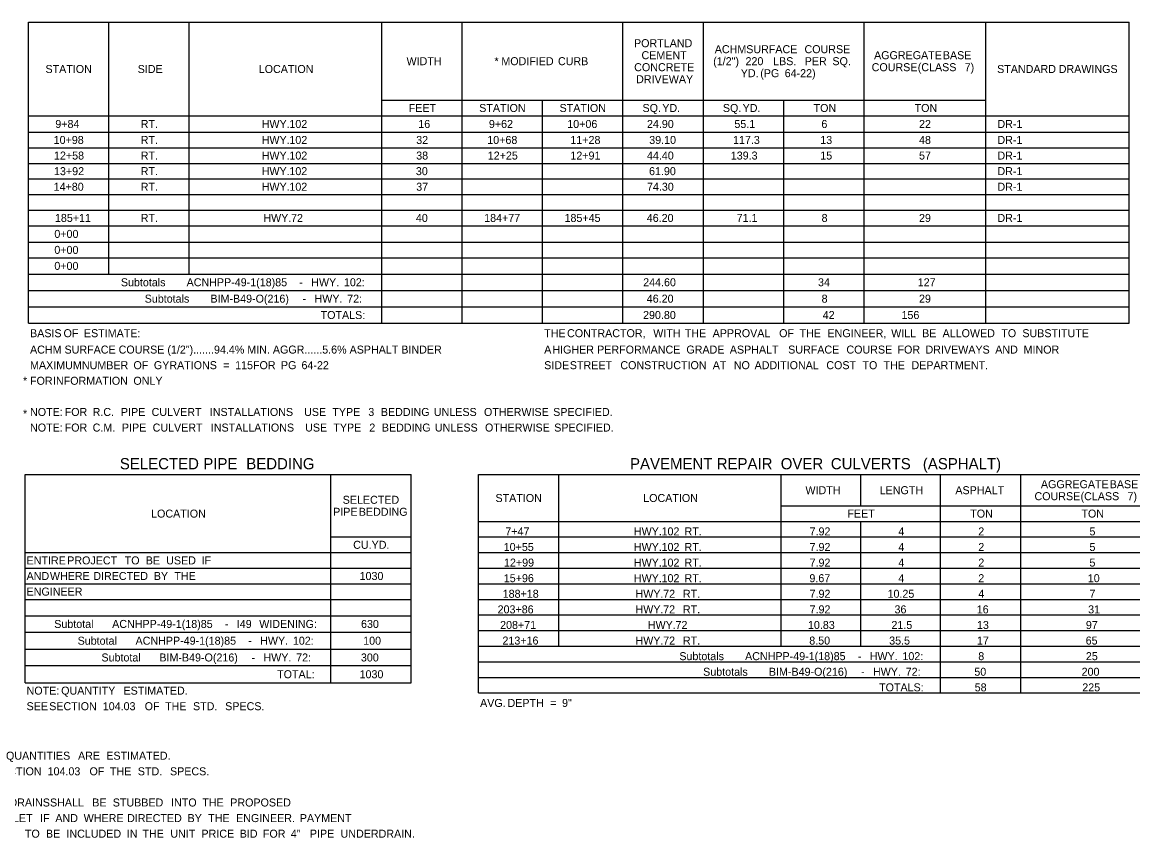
# Model space of a CAD drawing. Extents: x 1226561 to 1228164, y 151309 to 152305.
# Drawn here: x 1226933 to 1227627, y 151326 to 151836 of the extents above; entities that cross this region are included whole.
import ezdxf

# ---------------------------------------------------------------- set-up
doc = ezdxf.new("R2010")
doc.units = 0
doc.layers.add('R_Dimension', color=7, linetype='Continuous')

msp = doc.modelspace()

# ---------------------------------------------------------------- linework, layer by layer
at = {"layer": 'R_Dimension'}
for p, q in [((1226937.37, 151835.6), (1227625.23, 151835.6)), ((1226937.37, 151647.43), (1226937.37, 151835.6)), ((1226987.58, 151678.14), (1226987.58, 151835.6)), ((1227037.79, 151678.14), (1227037.79, 151835.6)), ((1227158.21, 151647.43), (1227158.21, 151835.6)), ((1227208.42, 151647.43), (1227208.42, 151835.6)), ((1227308.84, 151647.43), (1227308.84, 151835.6)), ((1227359.06, 151647.43), (1227359.06, 151835.6)), ((1227459.48, 151647.43), (1227459.48, 151835.6)), ((1227535.53, 151647.43), (1227535.53, 151835.6)), ((1227625.23, 151647.43), (1227625.23, 151835.6)), ((1227158.21, 151786.85), (1227535.53, 151786.85)), ((1227258.63, 151647.43), (1227258.63, 151786.85)), ((1227409.27, 151647.43), (1227409.27, 151786.85)), ((1226937.37, 151777.1), (1227625.23, 151777.1)), ((1227535.53, 151777.1), (1227625.23, 151777.1)), ((1226937.37, 151766.86), (1227625.23, 151766.86)), ((1226937.37, 151757.11), (1227625.23, 151757.11)), ((1226937.37, 151747.36), (1227625.23, 151747.36)), ((1226937.37, 151737.61), (1227625.23, 151737.61)), ((1226937.37, 151727.86), (1227625.23, 151727.86)), ((1226937.37, 151718.11), (1227625.23, 151718.11)), ((1226937.37, 151708.36), (1227625.23, 151708.36)), ((1226937.37, 151698.13), (1227625.23, 151698.13)), ((1226937.37, 151688.38), (1227625.23, 151688.38)), ((1226937.37, 151678.14), (1227625.23, 151678.14)), ((1226937.37, 151678.14), (1227625.23, 151678.14)), ((1226937.37, 151667.9), (1227625.23, 151667.9)), ((1226937.37, 151657.66), (1227625.23, 151657.66)), ((1226937.37, 151647.43), (1227625.23, 151647.43)), ((1226935.2, 151552.78), (1227176.51, 151552.78)), ((1226935.2, 151422.62), (1226935.2, 151552.78)), ((1227126.3, 151422.62), (1227126.3, 151552.78)), ((1227176.51, 151422.62), (1227176.51, 151552.78)), ((1227218.58, 151552.78), (1227646.11, 151552.78)), ((1227218.58, 151416.28), (1227218.58, 151552.78)), ((1227268.79, 151445.53), (1227268.79, 151552.78)), ((1227407.73, 151445.53), (1227407.73, 151552.78)), ((1227457.45, 151533.28), (1227457.45, 151552.78)), ((1227507.18, 151416.28), (1227507.18, 151552.78)), ((1227557.39, 151416.28), (1227557.39, 151552.78)), ((1227407.73, 151533.28), (1227646.11, 151533.28)), ((1227218.58, 151523.53), (1227646.11, 151523.53)), ((1227457.45, 151445.53), (1227457.45, 151523.53)), ((1227126.3, 151513.78), (1227176.51, 151513.78)), ((1227218.58, 151513.78), (1227646.11, 151513.78)), ((1226935.2, 151504.03), (1227176.51, 151504.03)), ((1227218.58, 151504.03), (1227646.11, 151504.03)), ((1226935.2, 151494.28), (1227176.51, 151494.28)), ((1227218.58, 151494.28), (1227646.11, 151494.28)), ((1226935.2, 151484.53), (1227176.51, 151484.53)), ((1227218.58, 151484.53), (1227646.11, 151484.53)), ((1226935.2, 151474.78), (1227176.51, 151474.78)), ((1227218.58, 151474.78), (1227646.11, 151474.78)), ((1226935.2, 151464.54), (1227176.51, 151464.54)), ((1227218.58, 151465.03), (1227646.11, 151465.03)), ((1226935.2, 151454.3), (1227176.51, 151454.3)), ((1227218.58, 151455.28), (1227646.11, 151455.28)), ((1227218.58, 151445.53), (1227646.11, 151445.53)), ((1226935.2, 151443.58), (1227176.51, 151443.58)), ((1226935.2, 151433.34), (1227176.51, 151433.34)), ((1227218.58, 151435.78), (1227646.11, 151435.78)), ((1227218.58, 151426.03), (1227646.11, 151426.03)), ((1226935.2, 151422.62), (1227176.51, 151422.62)), ((1227218.58, 151416.28), (1227646.11, 151416.28))]:
    msp.add_line(p, q, dxfattribs=at)

# ---------------------------------------------------------------- texts
for s, height, p in [('PORTLAND', 5, (1227315.74, 151819.98)), ('ACHM', 5, (1227366.2, 151816.23)), (' SURFACE', 5, (1227383.99, 151816.23)), (' COURSE', 5, (1227420.41, 151816.23)), ('WIDTH', 5, (1227173.59, 151808.73)), ('*', 5, (1227228.55, 151808.73)), (' MODIFIED', 5, (1227230.99, 151808.73)), (' CURB', 5, (1227266.35, 151808.73)), ('CEMENT', 5, (1227320.43, 151812.48)), ('(1/2")', 5, (1227365.21, 151808.73)), (' 220', 5, (1227383.56, 151808.73)), (' LBS.', 5, (1227400.8, 151808.73)), (' PER', 5, (1227420.53, 151808.73)), (' SQ.', 5, (1227437.85, 151808.73)), ('AGGREGATE', 5, (1227465.75, 151812.48)), (' BASE', 5, (1227506.86, 151812.48)), ('STATION', 5, (1226947.97, 151803.85)), ('SIDE', 5, (1227005.6, 151803.85)), ('LOCATION', 5, (1227081.25, 151803.85)), ('CONCRETE', 5, (1227315.84, 151804.98)), ('YD.', 5, (1227382.44, 151801.23)), (' (PG', 5, (1227392.75, 151801.23)), (' 64-22)', 5, (1227408.03, 151801.23)), ('COURSE', 5, (1227464.24, 151804.98)), (' (CLASS', 5, (1227491.17, 151804.98)), (' 7)', 5, (1227520.5, 151804.98)), ('STANDARD', 5, (1227542.63, 151803.85)), (' DRAWINGS', 5, (1227579.28, 151803.85)), ('DRIVEWAY', 5, (1227317.02, 151797.48)), ('FEET', 5, (1227174.95, 151779.48)), ('STATION', 5, (1227219.02, 151779.48)), ('STATION', 5, (1227269.23, 151779.48)), ('SQ.', 5, (1227321.06, 151779.48)), (' YD.', 5, (1227331.53, 151779.48)), ('SQ.', 5, (1227371.27, 151779.48)), (' YD.', 5, (1227381.74, 151779.48)), ('TON', 5, (1227427.94, 151779.48)), ('TON', 5, (1227491.07, 151779.48)), ('9+84', 5, (1226954.13, 151769.48)), ('RT.', 5, (1227007.49, 151769.48)), ('HWY.', 5, (1227083.1, 151769.48)), (' 102', 5, (1227098.53, 151769.48)), ('16', 5, (1227180.93, 151769.48)), ('9+62', 5, (1227225.06, 151769.48)), ('10+06', 5, (1227274.03, 151769.48)), ('24.90', 5, (1227323.83, 151769.48)), ('55.1', 5, (1227378.45, 151769.48)), ('6', 5, (1227432.82, 151769.48)), ('22', 5, (1227493.84, 151769.48)), ('DR-1', 5, (1227542.82, 151769.48)), ('10+98', 5, (1226953.1, 151759.49)), ('RT.', 5, (1227007.49, 151759.49)), ('HWY.', 5, (1227083.1, 151759.49)), (' 102', 5, (1227098.53, 151759.49)), ('32', 5, (1227179.65, 151759.49)), ('10+68', 5, (1227224.04, 151759.49)), ('11+28', 5, (1227275.98, 151759.49)), ('39.10', 5, (1227325.25, 151759.49)), ('117.3', 5, (1227377.63, 151759.49)), ('13', 5, (1227432.13, 151759.49)), ('48', 5, (1227493.84, 151759.49)), ('DR-1', 5, (1227542.82, 151759.49)), ('12+58', 5, (1226953.3, 151749.74)), ('RT.', 5, (1227007.49, 151749.74)), ('HWY.', 5, (1227083.1, 151749.74)), (' 102', 5, (1227098.53, 151749.74)), ('38', 5, (1227179.65, 151749.74)), ('12+25', 5, (1227224.35, 151749.74)), ('12+91', 5, (1227275.98, 151749.74)), ('44.40', 5, (1227323.83, 151749.74)), ('139.3', 5, (1227376.21, 151749.74)), ('15', 5, (1227432.13, 151749.74)), ('57', 5, (1227493.84, 151749.74)), ('DR-1', 5, (1227542.82, 151749.74)), ('13+92', 5, (1226953.3, 151739.99)), ('RT.', 5, (1227007.49, 151739.99)), ('HWY.', 5, (1227083.1, 151739.99)), (' 102', 5, (1227098.53, 151739.99)), ('30', 5, (1227179.43, 151739.99)), ('61.90', 5, (1227325.13, 151739.99)), ('DR-1', 5, (1227542.82, 151739.99)), ('14+80', 5, (1226953.08, 151730.24)), ('RT.', 5, (1227007.49, 151730.24)), ('HWY.', 5, (1227083.1, 151730.24)), (' 102', 5, (1227098.53, 151730.24)), ('37', 5, (1227179.65, 151730.24)), ('74.30', 5, (1227323.83, 151730.24)), ('DR-1', 5, (1227542.82, 151730.24)), ('185+11', 5, (1226953.89, 151710.74)), ('RT.', 5, (1227007.49, 151710.74)), ('HWY.', 5, (1227084.12, 151710.74)), (' 72', 5, (1227099.55, 151710.74)), ('40', 5, (1227179.43, 151710.74)), ('184+77', 5, (1227222.11, 151710.74)), ('185+45', 5, (1227272.32, 151710.74)), ('46.20', 5, (1227323.71, 151710.74)), ('71.1', 5, (1227379.87, 151710.74)), ('8', 5, (1227432.96, 151710.74)), ('29', 5, (1227493.82, 151710.74)), ('DR-1', 5, (1227542.82, 151710.74)), ('0+00', 5, (1226953.52, 151700.75)), ('0+00', 5, (1226953.52, 151690.75)), ('0+00', 5, (1226953.52, 151680.76)), ('Subtotals', 5, (1226995.1, 151670.52)), (' ACNHPP-49-1(18)85', 5, (1227034.31, 151670.52)), (' HWY.', 5, (1227112.19, 151670.52)), (' 102:', 5, (1227132.62, 151670.52)), ('244.60', 5, (1227321.47, 151670.52)), ('34', 5, (1227430.71, 151670.52)), ('127', 5, (1227493.02, 151670.52)), (' -', 5, (1227104.75, 151670.52)), ('Subtotals', 5, (1227009.98, 151660.28)), (' BIM-B49-O(216)', 5, (1227049.19, 151660.28)), (' -', 5, (1227106.79, 151660.28)), (' HWY.', 5, (1227114.23, 151660.28)), (' 72:', 5, (1227134.67, 151660.28)), ('46.20', 5, (1227323.71, 151660.28)), ('8', 5, (1227432.96, 151660.28)), ('29', 5, (1227493.82, 151660.28)), ('TOTALS:', 5, (1227119.9, 151650.05)), ('290.80', 5, (1227321.39, 151650.05)), ('42', 5, (1227433.64, 151650.05)), ('156', 5, (1227482.88, 151650.05)), ('BASIS', 5, (1226938.34, 151638.68)), (' OF', 5, (1226957.4, 151638.68)), (' ESTIMATE:', 5, (1226970.15, 151638.68)), ('THE', 5, (1227259.61, 151638.68)), (' CONTRACTOR,', 5, (1227272.05, 151638.68)), (' WITH', 5, (1227325.87, 151638.68)), (' THE', 5, (1227345.59, 151638.68)), (' APPROVAL', 5, (1227363.03, 151638.68)), (' OF', 5, (1227404.57, 151638.68)), (' THE', 5, (1227417.32, 151638.68)), (' ENGINEER,', 5, (1227434.76, 151638.68)), (' WILL', 5, (1227474.57, 151638.68)), (' BE', 5, (1227493.9, 151638.68)), (' ALLOWED', 5, (1227506.69, 151638.68)), (' TO', 5, (1227543.39, 151638.68)), (' SUBSTITUTE', 5, (1227556.54, 151638.68)), ('ACHM SURFACE COURSE (1/2").......94.4% MIN. AGGR......5.6% ASPHALT BINDER', 5, (1226938.34, 151628.44)), ('A', 5, (1227259.61, 151628.44)), (' HIGHER', 5, (1227262.87, 151628.44)), (' PERFORMANCE', 5, (1227290.83, 151628.44)), (' GRADE', 5, (1227346.61, 151628.44)), (' ASPHALT', 5, (1227373.74, 151628.44)), (' SURFACE', 5, (1227410.2, 151628.44)), (' COURSE', 5, (1227446.61, 151628.44)), (' FOR', 5, (1227478.54, 151628.44)), (' DRIVEWAYS', 5, (1227496.02, 151628.44)), (' AND', 5, (1227539.61, 151628.44)), (' MINOR', 5, (1227557.32, 151628.44)), ('MAXIMUM', 5, (1226938.34, 151618.69)), (' NUMBER', 5, (1226968.89, 151618.69)), (' OF', 5, (1227001.1, 151618.69)), (' GYRATIONS', 5, (1227013.86, 151618.69)), (' =', 5, (1227057.2, 151618.69)), (' 115', 5, (1227064.64, 151618.69)), (' FOR', 5, (1227075.78, 151618.69)), (' PG', 5, (1227093.26, 151618.69)), (' 64-22', 5, (1227106.1, 151618.69)), ('SIDE', 5, (1227259.61, 151618.69)), (' STREET', 5, (1227273.78, 151618.69)), (' CONSTRUCTION', 5, (1227305.35, 151618.69)), (' AT', 5, (1227363.07, 151618.69)), (' NO', 5, (1227376.22, 151618.69)), (' ADDITIONAL', 5, (1227389.21, 151618.69)), (' COST', 5, (1227434.05, 151618.69)), (' TO', 5, (1227456.65, 151618.69)), (' THE', 5, (1227469.8, 151618.69)), (' DEPARTMENT.', 5, (1227487.24, 151618.69)), ('*', 5, (1226933.95, 151608.94)), ('FOR', 5, (1226938.34, 151608.94)), (' INFORMATION', 5, (1226950.82, 151608.94)), (' ONLY', 5, (1227001.06, 151608.94)), ('*', 5, (1226933.95, 151588.44)), ('NOTE:', 5, (1226938.34, 151589.44)), (' FOR', 5, (1226958.11, 151589.44)), (' R.C.', 5, (1226975.59, 151589.44)), (' PIPE', 5, (1226993.26, 151589.44)), (' CULVERT', 5, (1227012.44, 151589.44)), (' INSTALLATIONS', 5, (1227048.82, 151589.44)), (' USE', 5, (1227107.75, 151589.44)), (' TYPE', 5, (1227125.35, 151589.44)), (' 3', 5, (1227147.83, 151589.44)), (' BEDDING', 5, (1227155.67, 151589.44)), (' UNLESS', 5, (1227188.82, 151589.44)), (' OTHERWISE', 5, (1227220.12, 151589.44)), (' SPECIFIED.', 5, (1227263.38, 151589.44)), ('NOTE:', 5, (1226938.34, 151579.69)), (' FOR', 5, (1226958.11, 151579.69)), (' C.M.', 5, (1226975.59, 151579.69)), (' PIPE', 5, (1226993.89, 151579.69)), (' CULVERT', 5, (1227013.07, 151579.69)), (' INSTALLATIONS', 5, (1227049.45, 151579.69)), (' USE', 5, (1227108.38, 151579.69)), (' TYPE', 5, (1227125.98, 151579.69)), (' 2', 5, (1227148.46, 151579.69)), (' BEDDING', 5, (1227156.3, 151579.69)), (' UNLESS', 5, (1227189.45, 151579.69)), (' OTHERWISE', 5, (1227220.75, 151579.69)), (' SPECIFIED.', 5, (1227264.01, 151579.69)), ('SELECTED', 7, (1226994.45, 151556.1)), (' PIPE', 7, (1227044, 151556.1)), (' BEDDING', 7, (1227070.84, 151556.1)), ('PAVEMENT', 7, (1227313.26, 151556.1)), (' REPAIR', 7, (1227364.8, 151556.1)), (' OVER', 7, (1227404.81, 151556.1)), (' CULVERTS', 7, (1227436.12, 151556.1)), (' (ASPHALT)', 7, (1227493.61, 151556.1)), ('AGGREGATE', 5, (1227570, 151544.28)), (' BASE', 5, (1227611.1, 151544.28)), ('WIDTH', 5, (1227422.86, 151540.53)), ('LENGTH', 5, (1227469.24, 151540.53)), ('ASPHALT', 5, (1227516.55, 151540.53)), ('COURSE', 5, (1227565.98, 151536.78)), (' (CLASS', 5, (1227592.91, 151536.78)), (' 7)', 5, (1227622.24, 151536.78)), ('SELECTED', 5, (1227133.7, 151534.53)), ('STATION', 5, (1227229.17, 151535.65)), ('LOCATION', 5, (1227321.5, 151535.65)), ('LOCATION', 5, (1227013.99, 151525.9)), ('PIPE', 5, (1227127.74, 151527.03)), (' BEDDING', 5, (1227141.91, 151527.03)), ('FEET', 5, (1227449.08, 151525.9)), ('TON', 5, (1227525.84, 151525.9)), ('TON', 5, (1227595.31, 151525.9)), ('7+47', 5, (1227235.34, 151514.78)), ('HWY.', 5, (1227315.66, 151514.78)), (' 102', 5, (1227331.09, 151514.78)), (' RT.', 5, (1227345.46, 151514.78)), ('7.92', 5, (1227425.46, 151514.78)), ('4', 5, (1227480.9, 151514.78)), ('2', 5, (1227530.86, 151514.78)), ('5', 5, (1227600.33, 151514.78)), ('CU.YD.', 5, (1227140.26, 151506.4)), ('10+55', 5, (1227234.31, 151505.03)), ('HWY.', 5, (1227315.66, 151505.03)), (' 102', 5, (1227331.09, 151505.03)), (' RT.', 5, (1227345.46, 151505.03)), ('7.92', 5, (1227425.46, 151505.03)), ('4', 5, (1227480.9, 151505.03)), ('2', 5, (1227530.86, 151505.03)), ('5', 5, (1227600.33, 151505.03)), ('ENTIRE', 5, (1226936.17, 151496.65)), (' PROJECT', 5, (1226959.71, 151496.65)), (' TO', 5, (1226995.62, 151496.65)), (' BE', 5, (1227008.77, 151496.65)), (' USED', 5, (1227021.56, 151496.65)), (' IF', 5, (1227043.69, 151496.65)), ('12+99', 5, (1227234.49, 151495.28)), ('HWY.', 5, (1227315.66, 151495.28)), (' 102', 5, (1227331.09, 151495.28)), (' RT.', 5, (1227345.46, 151495.28)), ('7.92', 5, (1227425.46, 151495.28)), ('4', 5, (1227480.9, 151495.28)), ('2', 5, (1227530.86, 151495.28)), ('5', 5, (1227600.33, 151495.28)), ('AND', 5, (1226936.17, 151486.9)), (' WHERE', 5, (1226948.89, 151486.9)), (' DIRECTED', 5, (1226976.01, 151486.9)), (' BY', 5, (1227013.81, 151486.9)), (' THE', 5, (1227026.68, 151486.9)), ('1030', 5, (1227144.26, 151486.9)), ('15+96', 5, (1227234.37, 151485.53)), ('HWY.', 5, (1227315.66, 151485.53)), (' 102', 5, (1227331.09, 151485.53)), (' RT.', 5, (1227345.46, 151485.53)), ('9.67', 5, (1227425.34, 151485.53)), ('4', 5, (1227480.9, 151485.53)), ('2', 5, (1227530.86, 151485.53)), ('10', 5, (1227599.29, 151485.53)), ('ENGINEER', 5, (1226936.17, 151477.15)), ('188+18', 5, (1227233.68, 151475.78)), ('HWY.', 5, (1227316.68, 151475.78)), (' 72', 5, (1227332.11, 151475.78)), (' RT.', 5, (1227344.44, 151475.78)), ('7.92', 5, (1227425.46, 151475.78)), ('10.25', 5, (1227474.16, 151475.78)), ('4', 5, (1227530.86, 151475.78)), ('7', 5, (1227600.33, 151475.78)), ('203+86', 5, (1227230.51, 151466.03)), ('HWY.', 5, (1227316.68, 151466.03)), (' 72', 5, (1227332.11, 151466.03)), (' RT.', 5, (1227344.44, 151466.03)), ('7.92', 5, (1227425.46, 151466.03)), ('36', 5, (1227478.51, 151466.03)), ('16', 5, (1227529.9, 151466.03)), ('31', 5, (1227599.51, 151466.03)), ('Subtotal', 5, (1226953.47, 151456.92)), (' ACNHPP-49-1(18)85', 5, (1226987.8, 151456.92)), (' -', 5, (1227058.23, 151456.92)), (' I49', 5, (1227065.67, 151456.92)), (' WIDENING:', 5, (1227079.69, 151456.92)), ('630', 5, (1227145.16, 151456.92)), ('208+71', 5, (1227232.07, 151456.28)), ('HWY.', 5, (1227324.38, 151456.28)), (' 72', 5, (1227339.81, 151456.28)), ('10.83', 5, (1227424.44, 151456.28)), ('21.5', 5, (1227476.6, 151456.28)), ('13', 5, (1227530.04, 151456.28)), ('97', 5, (1227598.09, 151456.28)), ('Subtotal', 5, (1226968.07, 151446.44)), (' ACNHPP-49-1(18)85', 5, (1227002.4, 151446.44)), (' HWY.', 5, (1227080.28, 151446.44)), (' 102:', 5, (1227100.71, 151446.44)), ('100', 5, (1227146.5, 151446.44)), ('213+16', 5, (1227233.54, 151446.53)), ('HWY.', 5, (1227316.68, 151446.53)), (' 72', 5, (1227332.11, 151446.53)), (' RT.', 5, (1227344.44, 151446.53)), ('8.50', 5, (1227425.25, 151446.53)), ('35.5', 5, (1227475.19, 151446.53)), ('17', 5, (1227530.04, 151446.53)), ('65', 5, (1227597.97, 151446.53)), (' -', 5, (1227072.84, 151446.44)), ('Subtotal', 5, (1226982.95, 151435.96)), (' BIM-B49-O(216)', 5, (1227017.28, 151435.96)), (' -', 5, (1227074.88, 151435.96)), (' HWY.', 5, (1227082.32, 151435.96)), (' 72:', 5, (1227102.76, 151435.96)), ('300', 5, (1227145.08, 151435.96)), ('Subtotals', 5, (1227344.07, 151436.78)), (' ACNHPP-49-1(18)85', 5, (1227383.28, 151436.78)), (' -', 5, (1227453.72, 151436.78)), (' HWY.', 5, (1227461.16, 151436.78)), (' 102:', 5, (1227481.59, 151436.78)), ('8', 5, (1227530.86, 151436.78)), ('25', 5, (1227598.09, 151436.78)), ('TOTAL:', 5, (1227092.72, 151425.48)), ('1030', 5, (1227144.26, 151425.48)), ('Subtotals', 5, (1227358.95, 151427.03)), (' BIM-B49-O(216)', 5, (1227398.16, 151427.03)), (' HWY.', 5, (1227463.2, 151427.03)), (' 72:', 5, (1227483.64, 151427.03)), ('50', 5, (1227528.4, 151427.03)), ('200', 5, (1227595.43, 151427.03)), (' -', 5, (1227455.76, 151427.03)), ('NOTE:', 5, (1226936.17, 151415.24)), (' QUANTITY', 5, (1226955.93, 151415.24)), (' ESTIMATED.', 5, (1226994.87, 151415.24)), ('TOTALS:', 5, (1227468.87, 151417.28)), ('58', 5, (1227528.62, 151417.28)), ('225', 5, (1227595.84, 151417.28)), ('SEE', 5, (1226936.17, 151405.49)), (' SECTION', 5, (1226948.45, 151405.49)), (' 104.03', 5, (1226981.92, 151405.49)), (' OF', 5, (1227008.1, 151405.49)), (' THE', 5, (1227020.86, 151405.49)), (' STD.', 5, (1227038.3, 151405.49)), (' SPECS.', 5, (1227058.41, 151405.49)), ('AVG.', 5, (1227219.55, 151407.53)), (' DEPTH', 5, (1227234.83, 151407.53)), (' =', 5, (1227261.48, 151407.53)), (' 9"', 5, (1227268.92, 151407.53)), (' QUANTITIES', 5, (1226921.46, 151374.55)), (' ARE', 5, (1226966.46, 151374.55)), (' ESTIMATED.', 5, (1226984.14, 151374.55)), (' SECTION', 5, (1226913.98, 151364.8)), (' 104.03', 5, (1226947.44, 151364.8)), (' OF', 5, (1226973.62, 151364.8)), (' THE', 5, (1226986.38, 151364.8)), (' STD.', 5, (1227003.82, 151364.8)), (' SPECS.', 5, (1227023.94, 151364.8)), ('UNDERDRAINS', 5, (1226901.7, 151345.3)), (' SHALL', 5, (1226948.94, 151345.3)), (' BE', 5, (1226975.36, 151345.3)), (' STUBBED', 5, (1226988.15, 151345.3)), (' INTO', 5, (1227024.61, 151345.3)), (' THE', 5, (1227044.14, 151345.3)), (' PROPOSED', 5, (1227061.58, 151345.3)), (' INLET', 5, (1226919.14, 151335.55)), (' IF', 5, (1226942.76, 151335.55)), (' AND', 5, (1226952.29, 151335.55)), (' WHERE', 5, (1226970, 151335.55)), (' DIRECTED', 5, (1226997.13, 151335.55)), (' BY', 5, (1227034.92, 151335.55)), (' THE', 5, (1227047.8, 151335.55)), (' ENGINEER.', 5, (1227065.24, 151335.55)), (' PAYMENT', 5, (1227105.04, 151335.55)), (' TO', 5, (1226933.27, 151325.8)), (' BE', 5, (1226946.42, 151325.8)), (' INCLUDED', 5, (1226959.22, 151325.8)), (' IN', 5, (1226996.93, 151325.8)), (' THE', 5, (1227006.7, 151325.8)), (' UNIT', 5, (1227024.14, 151325.8)), (' PRICE', 5, (1227043.59, 151325.8)), (' BID', 5, (1227067.48, 151325.8)), (' FOR', 5, (1227081.97, 151325.8)), (' 4"', 5, (1227099.45, 151325.8)), (' PIPE', 5, (1227111.34, 151325.8)), (' UNDERDRAIN.', 5, (1227130.51, 151325.8))]:
    msp.add_text(s, height=height, dxfattribs=at).set_placement(p)

doc.saveas('drawing.dxf')
